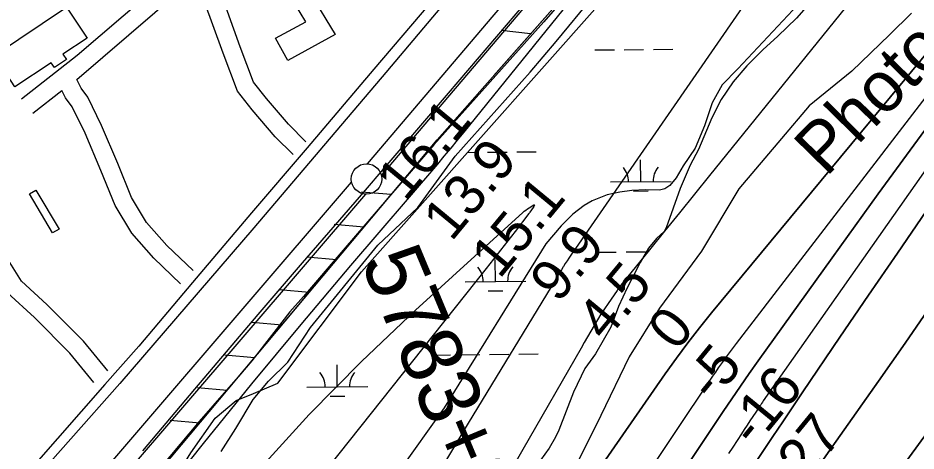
# Model space of a CAD drawing. Extents: x 3598634 to 3636690, y 517270 to 542944.
# Drawn here: x 3604186 to 3605662, y 529174 to 529886 of the extents above; entities that cross this region are included whole.
import ezdxf

# ---------------------------------------------------------------- set-up
doc = ezdxf.new("R2010")
doc.units = 0
for name, color, linetype in [('V-BLDG-OTLN', 7, 'Continuous'), ('V-FLOD-BASE', 7, 'Continuous'), ('V-LEVE-TOET', 7, 'Continuous'), ('V-RIVR-EDGE', 7, 'Continuous'), ('V-RIVR-IDEN', 7, 'Continuous'), ('V-RIVR-RANG', 7, 'Continuous'), ('V-ROAD-CNTR', 7, 'Continuous'), ('V-RRAP-FSHR', 7, 'Continuous'), ('V-SITE-VEGE', 7, 'Continuous'), ('V-SURV-IDEN', 7, 'Continuous'), ('V-SURV-LINE', 7, 'Continuous'), ('V-TOPO-DPTH', 7, 'Continuous'), ('V-TOPO-MINR', 7, 'Continuous'), ('V-TOPO-WATR', 7, 'Continuous'), ('V-WETL-SWMP', 7, 'Continuous')]:
    doc.layers.add(name, color=color, linetype=linetype)

msp = doc.modelspace()

# ---------------------------------------------------------------- linework, layer by layer
at = {"layer": 'V-BLDG-OTLN'}
for points in [[(3604707.7, 529858.6), (3604629.5, 529815.8), (3604609.4, 529852.5), (3604659.2, 529879.7), (3604640.5, 529910.5), (3604667.6, 529925.1)], [(3604147, 529824.2), (3604266.2, 529903.6), (3604299.9, 529852.9), (3604260.1, 529826.4), (3604265.9, 529817.7), (3604246, 529804.4), (3604240.8, 529812.2), (3604181.3, 529772.6)], [(3604243.2, 529532.3), (3604205.1, 529596.5), (3604215.8, 529602.9), (3604253.9, 529538.7)]]:
    msp.add_lwpolyline(points, close=True, dxfattribs=at)
at = {"layer": 'V-FLOD-BASE'}
msp.add_lwpolyline([(3605052.1, 529949), (3604893.1, 529762.5), (3604747.2, 529591), (3604653, 529483), (3604580.5, 529398.1), (3604476.6, 529275.7), (3604391.1, 529174.1)], dxfattribs=at)
at = {"layer": 'V-LEVE-TOET'}
for points in [[(3605056.3, 530112.1), (3604790.8, 529796.4), (3604573.6, 529540.7), (3604353.6, 529284.8), (3604111.5, 529011.5), (3603916.4, 528772.2)], [(3605168.3, 530015.7), (3605050.3, 529879.7)], [(3605050.3, 529879.7), (3604869.8, 529677.4), (3604720.6, 529504.1), (3604655.2, 529427.9), (3604632.9, 529402.5), (3604606.9, 529368.5), (3604570.5, 529321.8), (3604548.7, 529296.4), (3604525.3, 529269.3), (3604483.9, 529222.5), (3604421.3, 529147.5), (3604419.3, 529139.5), (3604415.7, 529128.7), (3604411.5, 529117.3), (3604385.3, 529089), (3604295.3, 528989), (3604145.9, 528823), (3604017, 528671.5)]]:
    msp.add_lwpolyline(points, dxfattribs=at)
at = {"layer": 'V-RIVR-EDGE'}
msp.add_lwpolyline([(3605654.7, 529893.7), (3605618.5, 529858.3), (3605556.4, 529798.4), (3605486.4, 529741.6), (3605441, 529687.8), (3605370.9, 529605.2), (3605309.4, 529502.4), (3605240.5, 529408.9), (3605190.7, 529328.7), (3605143.9, 529232), (3605107.6, 529158)], dxfattribs=at)
at = {"layer": 'V-ROAD-CNTR'}
for points in [[(3605050.3, 530130.1), (3604771, 529801.9), (3604661.3, 529672.6), (3604570.1, 529565.2), (3604473.3, 529450.7), (3604385.1, 529346.4), (3604329.2, 529282.9), (3604137.8, 529065.5), (3604133.8, 529061), (3603910.1, 528798.8), (3603670.9, 528524.4), (3603437, 528243.4)], [(3604192, 529752.8), (3604283.3, 529824.5), (3604434.6, 529954.9), (3604467.4, 529983.1)], [(3604659.4, 529682.5), (3604630.7, 529711.1), (3604594.4, 529753.7), (3604573.5, 529780.6), (3604551.5, 529838.3), (3604520.1, 529926.2), (3604502.7, 529973.7)], [(3604282.9, 529784.5), (3604454.1, 529932.2), (3604478.4, 529952.9)], [(3604638.2, 529661.3), (3604608.7, 529690.7), (3604571.2, 529734.7), (3604547, 529765.8), (3604523.4, 529827.9), (3604491.9, 529916), (3604478.4, 529952.9)], [(3604474.2, 529470.4), (3604431.1, 529511.9), (3604397.5, 529549.6), (3604372.8, 529590.8), (3604350.2, 529646.5), (3604323.7, 529709.2), (3604300.9, 529755.5), (3604289.9, 529770.3), (3604282.9, 529784.5)], [(3604210.5, 529729.2), (3604258.2, 529766.7)], [(3604453.4, 529448.7), (3604409.4, 529491.1), (3604373.2, 529531.8), (3604345.9, 529577.4), (3604322.4, 529635), (3604296.4, 529696.7), (3604275.2, 529739.8), (3604264.2, 529754.6), (3604258.2, 529766.7)], [(3604310.9, 529286.5), (3604271.7, 529334.5), (3604213.2, 529393.1), (3604168.9, 529433.8), (3604144.2, 529472.7), (3604123.4, 529509.2), (3604105.8, 529546.8), (3604080, 529584.5), (3604048.5, 529626.6), (3604028.2, 529666.9), (3604023.9, 529707), (3604029.5, 529737.4), (3604034.6, 529751.7)], [(3604334.1, 529305.4), (3604294, 529354.6), (3604233.9, 529414.8), (3604192.1, 529453.2), (3604169.9, 529488.2), (3604150, 529523), (3604131.9, 529561.7), (3604104.4, 529602), (3604074.1, 529642.5), (3604057.5, 529675.6), (3604054.2, 529705.9), (3604058.6, 529729.6), (3604062.9, 529741.6)]]:
    msp.add_lwpolyline(points, dxfattribs=at)
at = {"layer": 'V-RRAP-FSHR'}
for p, q in [((3605028.7, 529859.9), (3604980.2, 529865.4)), ((3604799.5, 529595.4), (3604750.9, 529599.6)), ((3604754.6, 529541.8), (3604705.9, 529546)), ((3604709.7, 529488.1), (3604661, 529492.3)), ((3604664.7, 529434.4), (3604616.1, 529438.6)), ((3604619.8, 529380.7), (3604571.1, 529384.9)), ((3604574.8, 529327.1), (3604526.2, 529331.3)), ((3604529.9, 529273.4), (3604481.3, 529277.6)), ((3604485, 529219.7), (3604436.3, 529223.9))]:
    msp.add_line(p, q, dxfattribs=at)
for points in [[(3604967.5, 529790.5), (3605090, 529929.6), (3605236.8, 530108), (3605464.9, 530364.9), (3605582.8, 530505.7)], [(3603091.9, 527329.5), (3603199.9, 527468.8), (3603247.5, 527548.8), (3603278.3, 527622.7), (3603286.7, 527683.9), (3603300.5, 527779.2), (3603315.4, 527834.6), (3603329.5, 527870), (3603360.8, 527909.2), (3603408.7, 527958.4), (3603635.1, 528229.7), (3603874.5, 528509.5), (3604166.6, 528854.3), (3604406.6, 529126.1), (3604875.1, 529685.7), (3605090, 529929.6)], [(3604263.2, 528963.7), (3604406.6, 529126.1), (3604800.2, 529596.2)]]:
    msp.add_lwpolyline(points, dxfattribs=at)
at = {"layer": 'V-SITE-VEGE'}
for p, q in [((3605070.5, 529847.3), (3605164.8, 529961.9)), ((3605467.6, 529907.4), (3605369.1, 529802.5)), ((3605028.2, 529796.9), (3605070.5, 529847.3)), ((3604904.7, 529658.6), (3605028.2, 529796.9)), ((3605369.1, 529802.5), (3605343.3, 529776.2)), ((3605343.3, 529776.2), (3605327.2, 529746.3)), ((3605327.2, 529746.3), (3605314.5, 529708.7)), ((3605314.5, 529708.7), (3605299.1, 529671.8)), ((3605299.1, 529671.8), (3605279.5, 529642.6)), ((3604843.1, 529574.1), (3604904.7, 529658.6)), ((3605279.5, 529642.6), (3605267.9, 529623.1)), ((3605267.9, 529623.1), (3605257.5, 529610.6)), ((3605249.1, 529605.1), (3605240.7, 529603)), ((3605257.5, 529610.6), (3605249.1, 529605.1)), ((3605154.3, 529594.9), (3605129.9, 529585.2)), ((3605175.2, 529599.7), (3605154.3, 529594.9)), ((3605194.8, 529602.4), (3605175.2, 529599.7)), ((3605217.7, 529603.1), (3605194.8, 529602.4)), ((3605240.7, 529603), (3605217.7, 529603.1)), ((3604777.8, 529512.3), (3604843.1, 529574.1)), ((3605116.7, 529577.6), (3605097.8, 529563)), ((3605129.9, 529585.2), (3605116.7, 529577.6)), ((3605097.8, 529563), (3605079, 529544.3)), ((3605079, 529544.3), (3605053.8, 529514.4)), ((3604666.7, 529376.8), (3604777.8, 529512.3)), ((3605053.8, 529514.4), (3604886.8, 529244.8)), ((3604629.5, 529320), (3604666.7, 529376.8)), ((3604598, 529288.5), (3604629.5, 529320)), ((3604572.6, 529258.4), (3604598, 529288.5)), ((3604544, 529210.9), (3604572.6, 529258.4)), ((3604886.8, 529244.8), (3604806.2, 529132.3)), ((3604520, 529173), (3604544, 529210.9))]:
    msp.add_line(p, q, dxfattribs=at)
at = {"layer": 'V-SURV-LINE'}
for points in [[(3604760.5, 529646.1), (3605801.6, 530872.1)], [(3605824.5, 530852.6), (3604783.3, 529626.7)], [(3603326, 527973.1), (3604734.6, 529615.8)], [(3604757.4, 529596.2), (3603348.8, 527953.6)]]:
    msp.add_lwpolyline(points, dxfattribs=at)
msp.add_circle((3604759, 529621.1), 25, dxfattribs=at)
at = {"layer": 'V-TOPO-DPTH'}
for points in [[(3604845.8, 528335.7), (3604867.3, 528367.4), (3604888.8, 528399.2), (3604910.3, 528430.9), (3605107.1, 528721.4), (3605163.3, 528804.6), (3605219.5, 528887.9), (3605275.5, 528971.4), (3605331.4, 529054.9), (3605410.1, 529172.8), (3605426.6, 529197.4), (3605443, 529221.9), (3605459.6, 529246.4), (3605476.1, 529270.9), (3605537, 529360.8), (3605584.1, 529430.1), (3605631.4, 529499.3), (3605678.9, 529568.4), (3605726.6, 529637.3), (3606120.2, 530204.3)], [(3606120.2, 530204.3), (3605726.6, 529637.3), (3605678.9, 529568.4), (3605631.4, 529499.3), (3605584.1, 529430.1), (3605537, 529360.8), (3605476.1, 529270.9), (3605459.6, 529246.4), (3605443, 529221.9), (3605426.6, 529197.4), (3605410.1, 529172.8), (3605331.4, 529054.9), (3605275.5, 528971.4), (3605219.5, 528887.9), (3605163.3, 528804.6), (3605107.1, 528721.4), (3604910.3, 528430.9), (3604888.8, 528399.2), (3604867.3, 528367.4), (3604845.8, 528335.7)], [(3605964.8, 530172.8), (3605326.2, 529401), (3605306.4, 529376.5), (3605287, 529351.6), (3605268.2, 529326.2), (3605249.9, 529300.6), (3605142.8, 529146.8)], [(3605142.8, 529146.8), (3605249.9, 529300.6), (3605268.2, 529326.2), (3605287, 529351.6), (3605306.4, 529376.5), (3605326.2, 529401), (3605964.8, 530172.8)], [(3605488, 530065.6), (3605102.4, 529506.8), (3605100, 529503.4), (3605099.2, 529502.2), (3605094.6, 529495.6), (3605091.6, 529491.1), (3605088.6, 529486.6), (3605085.6, 529482), (3605082.7, 529477.4), (3605082.3, 529476.6), (3605079.2, 529471.6), (3605076.1, 529466.6), (3605073, 529461.6), (3605070, 529456.6), (3604926.2, 529219.3), (3604869.4, 529124.9)], [(3605024.7, 528344), (3605083.8, 528420.9), (3605135.1, 528487.9), (3605186.4, 528554.8), (3605237.8, 528621.7), (3605289.1, 528688.7), (3605573.7, 529059.5), (3605586.9, 529076.9), (3605600.1, 529094.3), (3605613, 529111.8), (3605626, 529129.4), (3605745.9, 529294.1), (3605818.7, 529394.1), (3605891.6, 529494), (3605964.5, 529594), (3606037.5, 529693.9), (3606273.1, 530016.3)], [(3606273.1, 530016.3), (3606037.5, 529693.9), (3605964.5, 529594), (3605891.6, 529494), (3605818.7, 529394.1), (3605745.9, 529294.1), (3605626, 529129.4), (3605613, 529111.8), (3605600.1, 529094.3), (3605586.9, 529076.9), (3605573.7, 529059.5), (3605289.1, 528688.7), (3605237.8, 528621.7), (3605186.4, 528554.8), (3605135.1, 528487.9), (3605083.8, 528420.9), (3605024.7, 528344)], [(3604933.7, 528348.5), (3604946.8, 528367.3), (3605196.3, 528723.6), (3605248.4, 528797.4), (3605300.7, 528871.1), (3605353.4, 528944.5), (3605406.3, 529017.7), (3605494, 529138.2), (3605503.3, 529151), (3605512.5, 529163.9), (3605521.7, 529176.8), (3605530.9, 529189.7), (3605600.5, 529288.5), (3605644.1, 529351.1), (3605687.2, 529413.9), (3605729.7, 529477.3), (3605771.8, 529540.9), (3605859.2, 529674.6), (3605898.9, 529735), (3605938.7, 529795.4), (3605978.6, 529855.6), (3606018.7, 529915.8)], [(3606018.7, 529915.8), (3605978.6, 529855.6), (3605938.7, 529795.4), (3605898.9, 529735), (3605859.2, 529674.6), (3605771.8, 529540.9), (3605729.7, 529477.3), (3605687.2, 529413.9), (3605644.1, 529351.1), (3605600.5, 529288.5), (3605530.9, 529189.7), (3605521.7, 529176.8), (3605512.5, 529163.9), (3605503.3, 529151), (3605494, 529138.2), (3605406.3, 529017.7), (3605353.4, 528944.5), (3605300.7, 528871.1), (3605248.4, 528797.4), (3605196.3, 528723.6), (3604946.8, 528367.3), (3604933.7, 528348.5)], [(3605676.4, 529701.3), (3605600, 529596.6), (3605524.1, 529491.5), (3605402.4, 529321.8), (3605387.9, 529301.3), (3605373.4, 529280.6), (3605359.2, 529259.8), (3605345.1, 529238.9), (3605278.1, 529138.3)], [(3605278.1, 529138.3), (3605345.1, 529238.9), (3605359.2, 529259.8), (3605373.4, 529280.6), (3605387.9, 529301.3), (3605402.4, 529321.8), (3605524.1, 529491.5), (3605600, 529596.6), (3605676.4, 529701.3)]]:
    msp.add_lwpolyline(points, dxfattribs=at)
at = {"layer": 'V-TOPO-MINR'}
for points in [[(3605455.6, 530362.7), (3604918.8, 529698.1), (3604908.1, 529684.9), (3604897.3, 529671.8), (3604886.3, 529658.7), (3604875.4, 529645.7), (3604732.8, 529478.9), (3604651, 529382), (3604570.1, 529284.5), (3604490.4, 529186), (3604411.5, 529086.8), (3604219.9, 528842.7), (3604215.4, 528836.8), (3604211.1, 528830.8), (3604207, 528824.7), (3604203, 528818.4), (3604074.2, 528606.6), (3604034.4, 528543.7)], [(3605899.8, 530341.1), (3605322.5, 529626.6), (3605297.8, 529596.1), (3605273.2, 529565.6), (3605248.6, 529535.2), (3605224, 529504.7), (3605179.2, 529449.3), (3605177, 529446.5), (3605174.8, 529443.7), (3605172.7, 529440.8), (3605170.7, 529437.9), (3605156, 529416.6), (3605150, 529407.7), (3605144.2, 529398.6), (3605138.5, 529389.4), (3605133, 529380.1), (3605127.7, 529370.8), (3605122.3, 529361.4), (3605116.9, 529352), (3605111.6, 529342.7), (3605016, 529176.1), (3604962.5, 529083.6)], [(3606051.8, 530242.9), (3605366.7, 529350.5), (3605361.7, 529343.9), (3605356.6, 529337.2), (3605351.7, 529330.6), (3605346.7, 529323.9), (3605341.9, 529317.2), (3605337.1, 529310.4), (3605332.3, 529303.6), (3605327.7, 529296.7), (3605071.1, 528912.9), (3605019.1, 528834.7), (3604967.3, 528756.3), (3604916, 528677.7), (3604864.9, 528598.9), (3604796.4, 528492.6), (3604779.8, 528466.8), (3604763.1, 528441), (3604746.5, 528415.1), (3604729.8, 528389.3), (3604653.7, 528271.2)], [(3606120.2, 530204.3), (3605726.6, 529637.3), (3605678.9, 529568.4), (3605631.4, 529499.3), (3605584.1, 529430.1), (3605537, 529360.8), (3605476.1, 529270.9), (3605459.6, 529246.4), (3605443, 529221.9), (3605426.6, 529197.4), (3605410.1, 529172.8), (3605331.4, 529054.9), (3605275.5, 528971.4), (3605219.5, 528887.9), (3605163.3, 528804.6), (3605107.1, 528721.4), (3604910.3, 528430.9), (3604888.8, 528399.2), (3604867.3, 528367.4), (3604845.8, 528335.7)], [(3605488, 530065.6), (3605102.4, 529506.8), (3605100, 529503.4), (3605099.2, 529502.2), (3605094.6, 529495.6), (3605091.6, 529491.1), (3605088.6, 529486.6), (3605085.6, 529482), (3605082.7, 529477.4), (3605082.3, 529476.6), (3605079.2, 529471.6), (3605076.1, 529466.6), (3605073, 529461.6), (3605070, 529456.6), (3604926.2, 529219.3), (3604869.4, 529124.9)], [(3606273.1, 530016.3), (3606037.5, 529693.9), (3605964.5, 529594), (3605891.6, 529494), (3605818.7, 529394.1), (3605745.9, 529294.1), (3605626, 529129.4), (3605613, 529111.8), (3605600.1, 529094.3), (3605586.9, 529076.9), (3605573.7, 529059.5), (3605289.1, 528688.7), (3605237.8, 528621.7), (3605186.4, 528554.8), (3605135.1, 528487.9), (3605083.8, 528420.9), (3605024.7, 528344)], [(3606018.7, 529915.8), (3605978.6, 529855.6), (3605938.7, 529795.4), (3605898.9, 529735), (3605859.2, 529674.6), (3605771.8, 529540.9), (3605729.7, 529477.3), (3605687.2, 529413.9), (3605644.1, 529351.1), (3605600.5, 529288.5), (3605530.9, 529189.7), (3605521.7, 529176.8), (3605512.5, 529163.9), (3605503.3, 529151), (3605494, 529138.2), (3605406.3, 529017.7), (3605353.4, 528944.5), (3605300.7, 528871.1), (3605248.4, 528797.4), (3605196.3, 528723.6), (3604946.8, 528367.3), (3604933.7, 528348.5)], [(3605839.2, 529865.9), (3605411, 529256.1), (3605409.6, 529254), (3605408.2, 529252), (3605406.8, 529249.9), (3605405.4, 529247.8), (3605398.6, 529237.7), (3605393.8, 529230.5), (3605389, 529223.3), (3605384.3, 529216.1), (3605379.6, 529208.9), (3605375, 529201.8), (3605368, 529191.1), (3605361, 529180.3), (3605354, 529169.6)], [(3605676.4, 529701.3), (3605600, 529596.6), (3605524.1, 529491.5), (3605402.4, 529321.8), (3605387.9, 529301.3), (3605373.4, 529280.6), (3605359.2, 529259.8), (3605345.1, 529238.9), (3605278.1, 529138.3)], [(3605034.1, 529576.1), (3605033.1, 529574.4), (3605027.5, 529566.5), (3605026.7, 529565.4), (3605026.3, 529564.9), (3605025.9, 529564.4), (3605003.1, 529534.8), (3604991.3, 529519.6), (3604979.4, 529504.3), (3604967.5, 529489.2), (3604955.5, 529474), (3604403.3, 528779)], [(3604582.6, 529143.5), (3604664.8, 529234), (3604750.9, 529320.9), (3604839.5, 529405.3), (3605015.8, 529566), (3605018.3, 529568.1), (3605020.8, 529570.1), (3605023.5, 529572), (3605026.2, 529573.8), (3605033.9, 529578.7), (3605034.4, 529578.7), (3605034.7, 529578.6), (3605034.9, 529578.3), (3605034.9, 529577.9), (3605034.1, 529576.1)]]:
    msp.add_lwpolyline(points, dxfattribs=at)
at = {"layer": 'V-TOPO-WATR'}
msp.add_lwpolyline([(3605964.8, 530172.8), (3605326.2, 529401), (3605306.4, 529376.5), (3605287, 529351.6), (3605268.2, 529326.2), (3605249.9, 529300.6), (3605142.8, 529146.8)], dxfattribs=at)
at = {"layer": 'V-WETL-SWMP'}
for p, q in [((3605134.4, 529833.3), (3605166.4, 529833.6)), ((3605182.4, 529833.8), (3605214.4, 529834.1)), ((3605230.4, 529834.2), (3605262.4, 529834.5)), ((3604924.8, 529664.9), (3604942.1, 529665)), ((3604958, 529665.2), (3604990, 529665.5)), ((3605006, 529665.6), (3605038, 529665.9)), ((3605209.8, 529616.8), (3605209.5, 529652.8)), ((3605159.8, 529616.3), (3605259.8, 529617.2)), ((3605198, 529601.2), (3605222, 529601.5)), ((3605137.5, 529500.7), (3605169.5, 529501)), ((3605185.5, 529501.1), (3605217.5, 529501.4)), ((3604970.9, 529452.7), (3604970.5, 529488.7)), ((3604920.9, 529452.2), (3605020.9, 529453.1)), ((3604959, 529437.1), (3604983, 529437.4)), ((3604865.2, 529331.6), (3604897.1, 529331.9)), ((3604913.1, 529332.1), (3604945.1, 529332.4)), ((3604961.1, 529332.5), (3604993.1, 529332.8)), ((3605009.1, 529333), (3605041.1, 529333.3)), ((3604711, 529279.4), (3604710.7, 529315.4)), ((3604661, 529279), (3604761, 529279.9)), ((3604699.2, 529263.9), (3604723.2, 529264.1))]:
    msp.add_line(p, q, dxfattribs=at)
for points in [[(3603445.3, 527974.1), (3604040.8, 528632.6), (3604355.7, 529010.5), (3604453, 529142.2), (3604470.2, 529170.8), (3604510.3, 529228), (3604544.6, 529256.7), (3604573.3, 529268.1), (3604613.3, 529285.3), (3604750.8, 529468.5), (3605243.2, 530023.9)], [(3605485.2, 529908), (3605465.6, 529885.7), (3605434.9, 529855.9), (3605410.4, 529833.7), (3605383.9, 529807.3), (3605361.5, 529780.9), (3605341.9, 529751.7), (3605326.5, 529721.8), (3605304.8, 529669.6), (3605290.8, 529643.9), (3605274.7, 529605.6), (3605251.5, 529540.9), (3605248, 529534.6), (3605235.4, 529523.5), (3605222.2, 529507.6), (3605208.9, 529483.9), (3605187.1, 529442.2), (3605173.1, 529411.6), (3605160.5, 529377.5), (3605135.3, 529333.7), (3605117.8, 529309.4), (3605098.9, 529270.4), (3605075, 529207.8), (3605069.8, 529196.4), (3605059, 529178.6), (3605030.9, 529139)]]:
    msp.add_lwpolyline(points, dxfattribs=at)
for centre, start, end in [((3605154.6, 529616.7), 359.7615, 41.3052), ((3605265.1, 529617.8), 139.7615, 181.3052), ((3604915.6, 529452.6), 359.7615, 41.3052), ((3605026.1, 529453.7), 139.7615, 181.3052), ((3604655.8, 529279.4), 359.7615, 41.3052), ((3604766.3, 529280.4), 139.7615, 181.3052)]:
    msp.add_arc(centre, 35.2, start, end, dxfattribs=at)

# ---------------------------------------------------------------- texts
at = {"layer": 'V-RIVR-IDEN'}
msp.add_text('Photo', height=83, rotation=45.5564, dxfattribs=at).set_placement((3605514.3, 529623.2))
at = {"layer": 'V-RIVR-RANG'}
for s, rotation, p in [('16.1', 50.4483, (3604822.9, 529582.2)), ('13.9', 50.4483, (3604898.5, 529516.7)), ('15.1', 50.4483, (3604977.5, 529455.2)), ('9.9', 50.4483, (3605074.2, 529415.3)), ('4.5', 50.4483, (3605151.6, 529352)), ('0', 50.7334, (3605268.4, 529336.2)), ('-5', 50.7334, (3605328.5, 529251.7)), ('-16', 50.7334, (3605397.1, 529177.6)), ('-27', 50.7334, (3605462, 529099))]:
    msp.add_text(s, height=67, rotation=rotation, dxfattribs=at).set_placement(p)
at = {"layer": 'V-SURV-IDEN'}
msp.add_text('5783+05.4', height=100, rotation=292.6583, dxfattribs=at).set_placement((3604748.7, 529485.1))

doc.saveas('drawing.dxf')
